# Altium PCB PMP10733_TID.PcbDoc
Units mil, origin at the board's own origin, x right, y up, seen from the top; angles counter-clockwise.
Board outline 1500 x 1500 mil, 2 copper layers (Top Layer, Bottom Layer), stack 62 mil thick; 37 components, 13 nets, 72 pads, 37 vias.
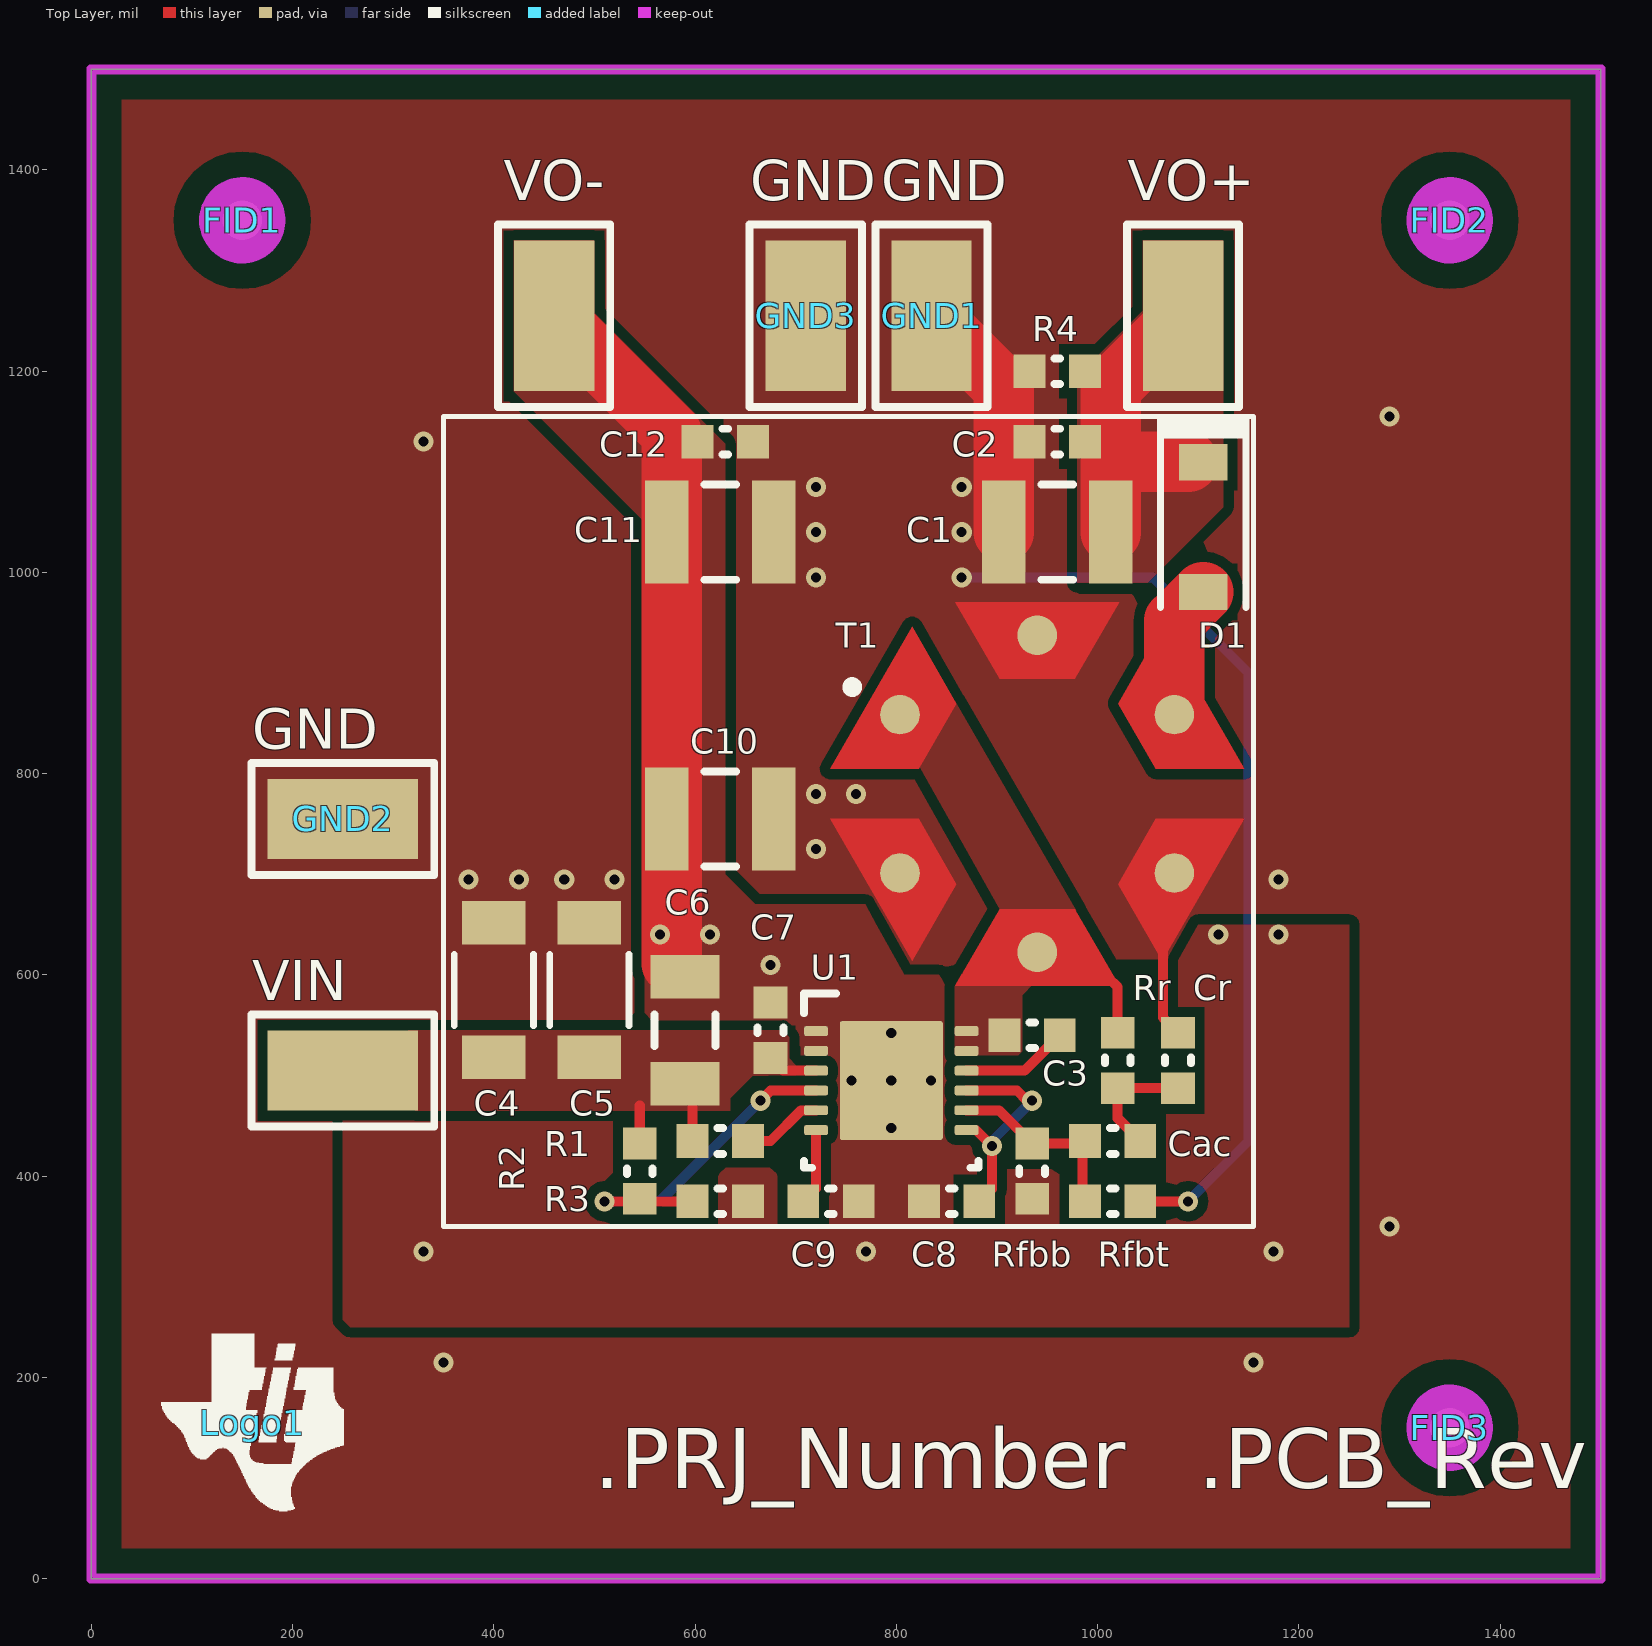
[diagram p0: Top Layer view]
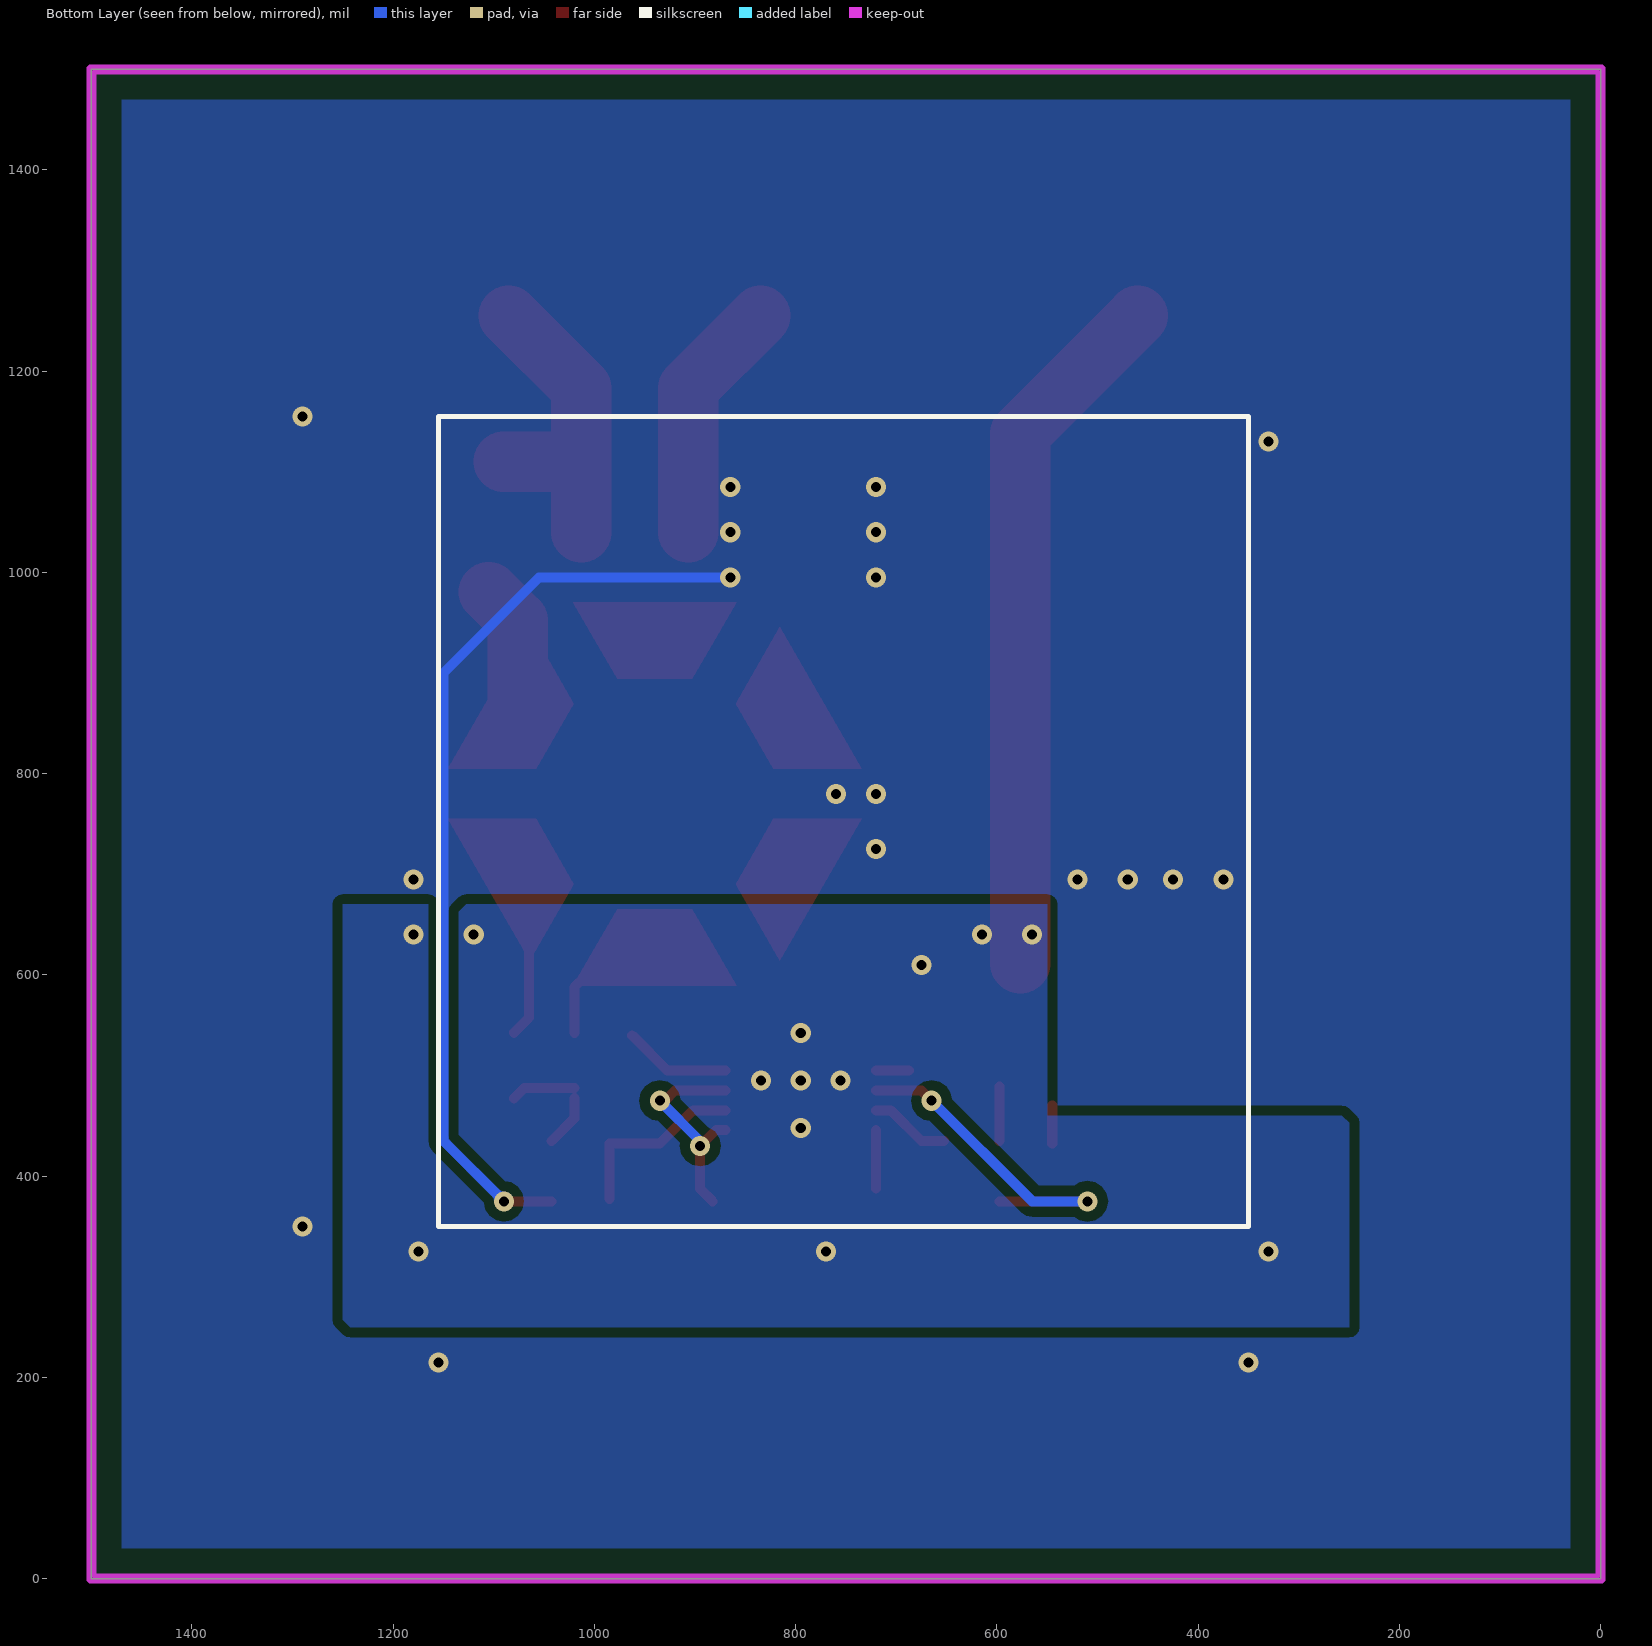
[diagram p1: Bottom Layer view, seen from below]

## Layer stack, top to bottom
Top Solder: solder mask 0.4, Solder Resist, Dk 3.5
Top Layer: signal copper 1.4
Dielectric1: core 59.2, FR-4, Dk 4.8
Bottom Layer: signal copper 1.4
Bottom Solder: solder mask 0.4, Solder Resist, Dk 3.5

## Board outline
0,0 1500,0 1500,1500 0,1500

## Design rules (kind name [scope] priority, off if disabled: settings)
AcuteAngle [All] p1: minimum=4.50000000000000E+0001 checktracksonly=FALSE
AssemblyTestPointUsage [All] p1: valid=2
Clearance Clearance_Keepouts [((IsTrack Or IsArc) And Not InPoly) And IsFree and IsKeepOut vs ((IsTrack Or IsArc) And Not InPoly) And IsFree and IsKeepOut] p1: gap=0
Clearance Clearance_BoardEdge_MountingHoles [OnCopper and InComponentClass('Mounting Holes') vs IsKeepOut] p2: gap=40
Clearance Clearance_BoardEdge_Poly [OnCopper and InPoly vs IsKeepOut] p3: gap=25
Clearance Clearance_BoardEdge [OnCopper and Not InComponentClass('Logo') and not InComponentClass('FiducialMark') and not InRegion(1000,500,4000,800) and Not IsKeepout vs IsKeepOut] p4: gap=75
Clearance Clearance_Poly [InPolygon] p5: gap=10
Clearance [All] p6: gap=7.87
ComponentClearance ComponentClearance_MountingHoles_FiducialMarks [InComponentClass('Mounting Holes') vs InComponentClass('FiducialMark')] p1: gap=50 collisioncheckmode=3 verticalgap=10 showdistances=FALSE
ComponentClearance ComponentClearance_Shunt [InComponentClass('Header') vs InComponentClass('Shunt')] p2: gap=0 collisioncheckmode=3 verticalgap=0 showdistances=FALSE
ComponentClearance ComponentClearance_Logo [InComponentClass('Logo')] p3: gap=50 collisioncheckmode=3 verticalgap=10 showdistances=FALSE
ComponentClearance ComponentClearance_ScrewToNut [(HasFootprint('NY PMS 440 0025 PH')) vs (HasFootprint('Keystone_1902C'))] p4: gap=5 collisioncheckmode=3 verticalgap=10 showdistances=FALSE
ComponentClearance ComponentClearance_MountingHoles [InComponentClass('Mounting Holes')] p5: gap=250 collisioncheckmode=3 verticalgap=100000 showdistances=FALSE
ComponentClearance ComponentClearance_SmallPassives [HasFootprint('0201*') or HasFootprint('0402*') or HasFootprint('0508') or HasFootprint('0603*') or HasFootprint('0612') or HasFootprint('0805*') or HasFootprint('0815*') or HasFootprint('0830*') or HasFootprint('1206*') or HasFootprint('1210*') or HasFootprint('1808*') or HasFootprint('1812*') or HasFootprint('1825*') or HasFootprint('2010*') or HasFootprint('2220*') or HasFootprint('2225*') or HasFootprint('2512*') or HasFootprint('2728*') or HasFootprint('3518*') vs HasFootprint('0201*') or HasFootprint('0402*') or HasFootprint('0508') or HasFootprint('0603*') or HasFootprint('0612') or HasFootprint('0805*') or HasFootprint('0815*') or HasFootprint('0830*') or HasFootprint('1206*') or HasFootprint('1210*') or HasFootprint('1808*') or HasFootprint('1812*') or HasFootprint('1825*') or HasFootprint('2010*') or HasFootprint('2220*') or HasFootprint('2225*') or HasFootprint('2512*') or HasFootprint('2728*') or HasFootprint('3518*')] p6: gap=15 collisioncheckmode=3 verticalgap=10 showdistances=FALSE
ComponentClearance ComponentClearance_THtoSMT [IsThruComponent vs IsSMTComponent] p7: gap=100 collisioncheckmode=3 verticalgap=30 showdistances=FALSE
ComponentClearance ComponentClearance_THtoTH [IsThruComponent vs IsThruComponent] p8: gap=118.11 collisioncheckmode=3 verticalgap=30 showdistances=FALSE
ComponentClearance [All] p9: gap=15 collisioncheckmode=3 verticalgap=10 showdistances=FALSE
DiffPairsRouting [All] p1: maxlimit=100 minlimit=10 mostfreqgap=10 toplayer_minwidth=15 toplayer_maxwidth=15 toplayer_prefwidth=15 bottomlayer_minwidth=15 bottomlayer_maxwidth=15 bottomlayer_prefwidth=15 maxuncoupledlength=1000
FabricationTestPointUsage TestPointUsage [All] p1: valid=2 allowmultiple=FALSE
FabricationTestpoint Testpoint [All] p1: side=3 testpointundercomponent=TRUE minsize=40 maxsize=100 preferedsize=60 minholesize=0 maxholesize=40 preferedholesize=32 testpointgrid=1 allowsidetop=TRUE allowsidebottom=TRUE usegrid=TRUE gridtolerance=0.01
FanoutControl Fanout_LCC [IsLCC] p1: bgadir=Out bgaviamode=Centered fanoutstyle=Auto fanoutdirection=Alternating viagrid=1 // Fanout_LCC (Default Rule)
FanoutControl Fanout_BGA [IsBGA] p2: bgadir=Out bgaviamode=Centered fanoutstyle=Auto fanoutdirection=Alternating viagrid=1 // Fanout_BGA (Default Rule)
FanoutControl Fanout_Default [All] p4: bgadir=Out bgaviamode=Centered fanoutstyle=Auto fanoutdirection=Alternating viagrid=1 // Fanout_Default (Default Rule)
FanoutControl Fanout_Small [(CompPinCount < 5)] p5: bgadir=Out bgaviamode=Centered fanoutstyle=Auto fanoutdirection=OutThenIn viagrid=1 // Fanout_Small (Default Rule)
HoleSize [All] p1: absolutevalues=TRUE maxlimit=251 minlimit=8 maxpercent=80.000 minpercent=20.000
MinimumAnnularRing MinimumAnnularRing_ThermalPadVias [IsVia and InAnyComponent] p1: minimumring=5
MinimumAnnularRing [All] p2: minimumring=5
MinimumSolderMaskSliver MinimumSolderMaskSliver_Logo [InComponentClass('Logo') vs InComponentClass('Logo')] p1: minsoldermaskwidth=0.7
MinimumSolderMaskSliver [All] p2: minsoldermaskwidth=3.94
PlaneConnect [All] p1: planeconnectstyle=Direct reliefexpansion=10 reliefentries=4 reliefconductorwidth=10 reliefairgap=10
PolygonConnect [All] p1: connectstyle=Direct reliefconductorwidth=10 reliefentries=4 polygonreliefangle="90 Angle" airgapwidth=10
RoutingVias ThermalPadVias [IsVia and InAnyComponent] p1: holewidth=7.87 width=19.68 viastyle="Through Hole" minholewidth=7.87 minwidth=19.68 maxholewidth=12.99 maxwidth=23.62
RoutingVias [All] p2: holewidth=16 width=34 viastyle="Through Hole" minholewidth=7.87 minwidth=20 maxholewidth=40 maxwidth=65
SilkToBoardRegionClearance [Not ((IsComment or IsDesignator) And (Hide <> 'False')) and not InRegion(1000,500,4000,800)] p1:
SilkToSilkClearance SilkToSilkClearance_Pb-FreeLogo [(HasFootprint('Pb-Free_Overlay_Medium') OR HasFootprint('Pb-Free_Overlay_Small')) vs (HasFootprint('Pb-Free_Overlay_Medium') OR HasFootprint('Pb-Free_Overlay_Small'))] p1: silktosilkclearance=0
SilkToSilkClearance [All] p2: silktosilkclearance=4
SilkToSolderMaskClearance "Silk to Solder Mask Opening" [All] p1: minsilkscreentomaskgap=3 clearancetoexposedcopper=FALSE
SolderMaskExpansion [All] p1: expansion=1.97
UnpouredPolygon [All] p1: allowunpoured=FALSE
Width [All] p1: maxlimit=100 minlimit=6 preferedwidth=10 checkconnectedcopper=TRUE
14 further rules are at their usual default settings.

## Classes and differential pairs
component class PMP10733_TID_Schematic: C1 C2 C3 C4 C5 C6 C7 C8 C9 C10 C11 C12 Cac Cr D1 GND1 GND2 GND3 R1 R2 R3 R4 Rfbb Rfbt Rr T1 U1 Vin VO+ VO-
component class Logo: Logo1
component class PMP10733_TID_Hardware: FID1 FID2 FID3 Logo1 ZZ2 ZZ3 ZZ4
component class FiducialMark: FID1 FID2 FID3
component class AssemblyNote: ZZ2 ZZ3 ZZ4

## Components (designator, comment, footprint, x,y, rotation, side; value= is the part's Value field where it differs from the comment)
C1 "GRM32ER71E226KE15L" 1210L 960,1040 r180 top
C2 "C1608X7R1H104K" 0603L 960,1130 r180 top
C3 "C1608X7R1H103K" 0603L 935,540 r180 top
C4 "C3216X7R1E106M160AE" 1206_190 400,585 r90 top
C5 "C3216X7R1E106M160AE" 1206_190 495,585 r90 top
C6 "GRM31CR71H475KA12L" 1206L 590,545 r90 top
C7 "C1608X7R1H104K" 0603L 675,545 r90 top
C8 "C1608X7R1E105K080AB" 0603L 855,375 r0 top
C9 "C1608X7R1H103K" 0603L 735,375 r0 top
C10 "GRM32ER71E226KE15L" 1210L 625,755 r180 top
C11 "" 1210L 625,1040 r180 top
C12 "C1608X7R1H104K" 0603L 630,1130 r180 top
Cac "C1608X7R1H102K" 0603L 1015,435 r180 top
Cr "GRM188R71H103KA01D" 0603L 1080,515 r270 top
D1 "RB160M-60TR" SOD-123 1105,1045 r270 top
FID1 "Fiducial" Fiducial10-20 150,1350 r0 top
FID2 "Fiducial" Fiducial10-20 1350,1350 r0 top
FID3 "Fiducial" Fiducial10-20 1350,150 r0 top
GND1 "GND" Keystone_5019 835,1255 r90 top
GND2 "GND" Keystone_5019 250,755 r0 top
GND3 "GND" Keystone_5019 710,1255 r90 top
Logo1 "Texas Instruments" TI_Symbol_Overlay_Small 160,155 r0 top
R1 "CRCW0603768KFKEA" 0603L 625,435 r0 top
R2 "CRCW060349K9FKEA" 0603L 545,405 r90 top
R3 "CRCW060322K6FKEA" 0603L 625,375 r180 top
R4 "CRCW06033K01FKEA" 0603L 960,1200 r0 top
Rfbb "CRCW060320K0FKEA" 0603L 935,405 r90 top
Rfbt "CRCW0603133KFKEA" 0603L 1015,375 r0 top
Rr "CRCW060320K0FKEA" 0603L 1020,515 r270 top
T1 "TA7848-AE" LPH8045-223 940,780 r60 top
U1 "LM5160DNTR" DNT0012B 795,495 r0 top
VIN "TESTPOINT" Keystone_5019 250,505 r0 top (schematic designator Vin)
VO+ "TESTPOINT" Keystone_5019 1085,1255 r90 top
VO- "TESTPOINT" Keystone_5019 460,1255 r90 top
ZZ2 "These assemblies are ESD sensitive, ESD precautions shall be observed." AssemblyNote 90,1994.11 r0 top
ZZ3 "These assemblies must be clean and free from flux and all contaminants. Use of no clean flux is not acceptable." AssemblyNote 90,1905.56 r0 top
ZZ4 "These assemblies must comply with workmanship standards IPC-A-610 Class 2, unless otherwise specified." AssemblyNote 90,1817 r0 top

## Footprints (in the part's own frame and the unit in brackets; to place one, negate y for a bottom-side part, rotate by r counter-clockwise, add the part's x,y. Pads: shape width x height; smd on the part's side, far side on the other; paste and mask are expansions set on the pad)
0603L [mm] "0603 from SM-752 data"
  rect 0.8x0.85 smd: 1(-0.7,0) 2(0.7,0)
  silkscreen extent -0.07,-0.33 0.07,0.33, body extent -0.87,-0.47 0.87,0.47, height 1
1206_190 [mm] "1206_190"
  rect 1.1x1.6 smd: 1(-1.7,0) 2(1.7,0)
  silkscreen extent -0.9,-1 0.9,1, body extent -1.75,-0.95 1.75,0.95, height 1.9
1206L [mm] "1206 from SM-752 data"
  rect 1.1x1.75 smd: 1(-1.35,0) 2(1.35,0)
  silkscreen extent -0.4,-0.77 0.4,0.77, body extent -1.7,-0.9 1.7,0.9, height 1.35
1210L [mm] "1210 from SM-752 data"
  rect 1.1x2.6 smd: 1(-1.35,0) 2(1.35,0)
  silkscreen extent -0.4,-1.2 0.4,1.2, body extent -1.7,-1.35 1.7,1.35, height 1.35
AssemblyNote [mil] "Assembly Note"
DNT0012B [mm] "SON, 12-Leads, Body 4x4mm, Pitch 0.5mm"
  rrect40% 0.6x0.25 smd: 1(-1.9,1.25) 2(-1.9,0.75) 3(-1.9,0.25) 4(-1.9,-0.25) 5(-1.9,-0.75) 6(-1.9,-1.25) 7(1.9,-1.25) 8(1.9,-0.75) 9(1.9,-0.25) 10(1.9,0.25) 11(1.9,0.75) 12(1.9,1.25)
  rrect4% 2.6x3 smd paste-1.3: 13(0,0)
  silkscreen extent -2.2,-2.2 2.2,2.2, body extent -2.05,-2.05 2.05,2.05, height 0.81
Fiducial10-20 [mm]
  round 1 smd mask+0.5: 1(0,0)
  Top Layer keep-out circle w1.178: c0,0 r0.5
Keystone_5019 [mm] "Test Point, Miniature, SMT"
  rect 3.8x2.03 smd: 1(0,0)
  silkscreen extent -2.31,-1.42 2.31,1.42, body extent -1.9,-1.02 1.9,1.02, height 2.29
LPH8045-223 [mm] "SMD, 6-Leads, Body 8.76x8.05mm"
  round 1 smd: 1(0,4) 2(-3.464,2) 3(-3.464,-2) 4(0,-4) 5(3.464,-2) 6(3.464,2)
  Top Layer region: -0.95,2.91 -2.07,4.84 2.07,4.84 0.95,2.91
  Top Layer region: -2.995,0.632 -5.227,0.627 -3.157,4.213 -2.045,2.278
  Top Layer region: -2.045,-2.278 -3.157,-4.213 -5.227,-0.627 -2.995,-0.632
  Top Layer region: 0.95,-2.91 2.07,-4.84 -2.07,-4.84 -0.95,-2.91
  Top Layer region: 2.995,-0.632 5.227,-0.627 3.157,-4.213 2.045,-2.278
  Top Layer region: 2.045,2.278 3.157,4.213 5.227,0.627 2.995,0.632
  silkscreen extent -0.12,5.27 0.12,5.51, body extent -4.03,-4.38 4.03,4.38, height 4.71
SOD-123 [mm] "On Semi recommended land pattern"
  rect 0.915x1.22 smd: 1(-1.637,0) 2(1.637,0)
  silkscreen extent -2.74,-1.17 2.03,1.17, body extent -1.93,-0.9 1.93,0.9, height 1.35
TI_Symbol_Overlay_Small [mil]
  silkscreen extent -90,-88 91,88

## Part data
C1 C10: "CAP, CERM, 22uF, 25V, +/-10%, X7R, 1210"
C2 C7 C12: "CAP, CERM, 0.1uF, 50V, +/-10%, X7R, 0603"
C3 C9 Cr: "CAP, CERM, 0.01uF, 50V, +/-10%, X7R, 0603"
C4 C5: "CAP, CERM, 10 µF, 25 V, +/- 20%, X7R, 1206_190"
C6: "CAP, CERM, 4.7 µF, 50 V, +/- 10%, X7R, 1206"
C8: "CAP, CERM, 1uF, 25V, +/-10%, X7R, 0603"
C11: library part GRM32ER71E226KE15L, "CAP, CERM, 22uF, 25V, +/-10%, X7R, 1210"
Cac: "CAP, CERM, 1000pF, 50V, +/-10%, X7R, 0603"
D1: "Diode, Schottky, 60 V, 1 A, SOD-123"
FID1 FID2 FID3: "Fiducial mark.  There is nothing to buy or mount."
GND1 GND2 GND3 VIN VO+ VO-: library part 5019, "Test Point, Miniature, SMT"
Logo1: library part TI_Logo, "Texas Instrument Corporate Signature"
R1: "RES, 768 k, 1%, 0.1 W, 0603"
R2: "RES, 49.9 k, 1%, 0.1 W, 0603"
R3: "RES, 22.6 k, 1%, 0.1 W, 0603"
R4: "RES, 3.01 k, 1%, 0.1 W, 0603"
Rfbb Rr: "RES, 20.0 k, 1%, 0.1 W, 0603"
Rfbt: "RES, 133 k, 1%, 0.1 W, 0603"
T1: "Coupled Inductor, 22uH, 1.35A Irms, 2A Isat, 1:1.05 turns ratio, LPH8045 Hexagonal Package"
U1: "Wide Input 65V, 1.5A Synchronous Step-Down DC-DC Converter, DNT0012B"
ZZ2 ZZ3 ZZ4: library part AssemblyNote

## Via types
v1: diameter 20, hole 10, Top Layer to Bottom Layer, 26 vias
v2: diameter 20, hole 10, Top Layer to Bottom Layer, tented both sides, 11 vias

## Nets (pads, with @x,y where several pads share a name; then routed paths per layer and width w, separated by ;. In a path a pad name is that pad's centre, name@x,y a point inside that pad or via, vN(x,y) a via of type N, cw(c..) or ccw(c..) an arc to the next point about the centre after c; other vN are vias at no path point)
BST: C3.1 U1.10 | length 107.3
  Top Layer w10: U1.10 927.4,504.84 C3.1
FB: Cac.2 Rfbb.2 Rfbt.1 U1.8 | length 183.9
  Top Layer w10: U1.8 902.09,465.47 Rfbb.2 985,432.56 Rfbt.1@985,377.44
GND: C1.2 C2.2 C4.2 C5.2 C10.1 C11.1 C12.1 Cr.1 GND1.1 GND2.1 GND3.1 R4.1 Rfbt.2 T1.2 T1.4 T1.6 | length 1265.1
  Top Layer w10: Rfbt.2 v1(1090,375) ; 1065,635 1065,557.56 Cr.1
  Top Layer w60: GND1.1 906.85,1183.15 C1.2
  Bottom Layer w10: v1(865,995) 1055,995 1150,900 1150,435 v1(1090,375)
  other v1: 375,695 425,695 470,695 520,695 720,725 720,780 760,780 720,995 720,1040 865,1040 720,1085 865,1085
  other v2: 350,215 1155,215 1290,350 1180,695 330,1130 1290,1155
NetCac_1: Cac.1 Cr.2 Rr.2 | length 115.9
  Top Layer w10: Rr.2@1020,477.44 1020,457.56 Cac.1 ; Rr.2 1070,487.44 Cr.2@1080,477.44
NetD1_2: D1.2 T1.5 | length 133.6
  Top Layer w60: T1.5 1076.38,951.91 D1.2
RON: R1.2 U1.5 | length 80.3
  Top Layer w10: R1.2 675,435 705.47,465.47 U1.5
SS: C9.1 U1.6 | length 58
  Top Layer w10: C9.1@720.2,387.76 U1.6
SW: C3.2 Rr.1 T1.1 T1.3 U1.11 U1.12 | length 59.6
  Top Layer w10: 1010,598 1020,588 Rr.1
UVLO: R2.1 R3.2 U1.4 | length 343.3
  Top Layer w10: v1(510,375) R3.2 ; v1(665,475) 675.16,485.16 U1.4
  Bottom Layer w10: v1(510,375) 565,375 v1(665,475)
VCC: C8.2 U1.7 U1.9 | length 222.9
  Top Layer w10: U1.7 879.21,445.79 v1(895,430) 895,387.44 C8.2 ; U1.9 919.84,485.16 930,475 v1(935,475)
  Bottom Layer w10: v1(895,430) 895,435 v1(935,475)
VIN: C4.1 C5.1 C6.1 C7.1 R1.1 R2.2 U1.3 VIN.1 | length 124.3
  Top Layer w10: R2.2 545,470 ; R1.1 C6.1@597.44,489.29 ; C7.1@687.6,504.84 U1.3
VO+: C1.1 C2.1 D1.1 R4.2 VO+.1 | length 314.8
  Top Layer w60: C1.1 1013.15,1183.15 VO+.1 ; 1020,1110 D1.1@1090,1110
VO-: C6.2 C7.2 C8.1 C9.2 C10.2 C11.2 C12.2 R3.1 Rfbb.1 U1.1 U1.2 U1.13 VO-.1 | length 692.1
  Top Layer w60: VO-.1 576.85,1138.15 576.85,1040 576.85,755 C6.2@576.85,611.3
  other v1: 795,447.76 755.63,495 795,495 834.37,495 795,542.25 675,610 565,640 615,640
  other v2: 330,325 770,325 1175,325 1120,640 1180,640
pads on no net: FID1.1 FID2.1 FID3.1

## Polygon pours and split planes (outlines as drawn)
GND on Top Layer "Top Layer-GND" (solid, remove dead copper, pour order 17): 0,1500 0,0 1500,0 1500,1500
VO- on Top Layer "Top Layer-VO-" (solid, remove dead copper, pour order 16): 250,455 250,250 1250,250 1250,650 1100,650 1072.22,600 807.78,600 780,650 768.89,670 760,670 700,670 700,455
VO- on Top Layer "Top Layer-VO-" (solid, remove dead copper, pour order 14): 705,550 550,550 550,950 550,1050 420,1180 420,1330 500,1330 500,1258 630,1128 630,890 630,700 660,670 710,670 720,670 730,670 730,520 705,520
VO+ on Top Layer "Top Layer-VO+" (solid, remove dead copper, pour order 13): 980,990 980,1195 1045,1260 1045,1330 1125,1330 1125,1080 1125,1065 1050,990
SW on Top Layer "Top Layer-SW" (solid, remove dead copper, pour order 12): 858,588.94 858,518 925,518 925,580 946,601 865,601
VIN on Top Layer "Top Layer-VIN" (solid, remove dead copper, pour order 11): 315,545 693.71,545 693.68,516.95 700.63,510 705,510 710,510 710,500 657.36,500 635.43,478.07 635,477.64 635,465 315,465
SW on Top Layer "Top Layer-SW" (solid, remove dead copper, pour order 10): 816.85,818.56 908.69,655 983.83,655 853.03,881.24
GND on Bottom Layer "Bottom Layer-GND" (solid, remove dead copper, pour order 18): 0,0 0,1500 1500,1500 1500,0
VO- on Bottom Layer "Top Layer-VO-" (solid, remove dead copper, pour order 15): 250,460 250,250 1250,250 1250,670 550,670 550,460

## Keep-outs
Keep-Out Layer:
  lines w5: -2.5,0 ccw(c0,0) 0,-2.5 ; -2.5,0 ccw(c0,0) 0,-2.5 ; -2.5,0 -2.5,1500 ; -2.5,1500 cw(c0,1500) 0,1502.5 ; -2.5,1500 cw(c0,1500) 0,1502.5 ; 0,-2.5 1500,-2.5 ; 0,1502.5 1500,1502.5 ; 1500,-2.5 ccw(c1500,0) 1502.5,0 ; 1500,-2.5 ccw(c1500,0) 1502.5,0 ; 1500,1502.5 cw(c1500,1500) 1502.5,1500 ; 1500,1502.5 cw(c1500,1500) 1502.5,1500 ; 1502.5,0 1502.5,1500 ; 2.5,2.5 1497.5,2.5 1497.5,1497.5 2.5,1497.5 2.5,2.5
  text ".Layer_Name" at 577,-858.49 h60

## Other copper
Top Layer:
  pour cut-out: 1015,403.46 1068.19,403.46 1068.19,350 1015,350
  pour cut-out: 1015,615 1080,615 1080,565 1015,565
  text ".Layer_Name" at 577,-858.49 h60
Bottom Layer:
  text ".Layer_Name" at 577,-858.49 h60

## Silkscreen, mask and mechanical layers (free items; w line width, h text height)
Top Overlay:
  lines w5: 350,350 1155,350 1155,1155 350,1155 350,350
  text ".PRJ_Number" at 500,90 h60
  text ".PCB_Rev" at 1100,90 h60
  text ".Layer_Name" at 577,-858.49 h60
Bottom Overlay:
  lines w5: 350,350 350,1155 1155,1155 1155,350 350,350
  text ".Layer_Name" at 577,-858.49 h60
Top Paste:
  text ".Layer_Name" at 577,-858.49 h60
Bottom Paste:
  text ".Layer_Name" at 577,-858.49 h60
Top Solder:
  text ".Layer_Name" at 577,-858.49 h60
  text ".Layer_Name" at 577,-858.49 h60
Bottom Solder:
  text ".Layer_Name" at 577,-858.49 h60
Drill Guide:
  text ".Layer_Name" at 577,-858.49 h60
M1 Board Outline:
  the board outline again, w10
  text ".Layer_Name" at 577,-858.49 h60
M2 Board Dimensions:
  rectangle: 0,-275 125,-150
  rectangle: 125,-400 500,-275
  lines w7: 0,-275 1000,-275 ; 125,-400 125,-150 ; 250,-400 250,-150 ; 500,-400 500,-150 ; 750,-400 750,-150 ; 0,-400 1000,-400 1000,-150 0,-150 0,-400
  text ".Layer_Name" at 577,-858.49 h60
M3 3D STEP Top:
  text ".Layer_Name" at 577,-858.49 h60
M4 3D STEP Bottom:
  text ".Layer_Name" at 577,-858.49 h60
M5 Assembly Top:
  lines w10: -292,-930.17 6308,-930.17 ; -292,-726.83 6310,-726.83 ; -292,-523.5 -292,-1133.5 3713,-1133.5 6310,-1133.5 6310,-523.5 -291.5,-523.5 -291.5,-1133.5 1284,-1133.5 ; 2173,-1133.5 2173,-523.5 ; 3440,-726.83 3440,-523.5 ; 4280,-726.83 4280,-523.5 ; 4902,-1140 4902,-937.17
  text "COMPONENTS MARKED 'DNP' SHOULD NOT BE POPULATED." at 1153.5,-318.5 h60
  text "ASSEMBLY VARIANT:" at 1153,-434 h60
  text ".VariantName" at 2189,-434 h60
  text "PCB VIEWED FROM TOP SIDE" at -228.5,-655.67 h60
  text "BOARD #:" at 2248,-655.67 h60
  text ".PRJ_Number" at 2793.5,-655.67 h60
  text "REV:" at 3638,-655.67 h60
  text ".PCB_Rev" at 3929.5,-655.67 h60
  text "SVN REV:" at 4476,-655.67 h60
  text ".VersionControl_RevNumber" at 4982,-655.67 h60
  text "TID #:" at 2248,-859 h60
  text ".TID" at 2793.5,-859 h60
  text "PLOT NAME =" at -228.5,-1064.34 h60
  text ".plot_File_Name" at 577,-1064.34 h60
  text "GENERATED    :" at 2250,-1064.34 h60
  text ".Print_Date" at 3119.5,-1064.34 h60
  text ".Print_Time" at 3848.5,-1064.34 h60
  text "TEXAS INSTRUMENTS" at 5113,-1064.34 h60
M6 Assembly Bottom:
  lines w10: -292.5,-727.33 6309.5,-727.33 ; -290.5,-930.67 6309.5,-930.67 ; 1115.5,-1140.5 1115.5,-937.67 ; 1737.5,-727.33 1737.5,-524 ; 2577.5,-727.33 2577.5,-524 ; 3844.5,-1134 3844.5,-524 ; 4733.5,-1134 6309,-1134 6309,-524 -292.5,-524 -292.5,-1134 2304.5,-1134 6309.5,-1134 6309.5,-524
  text "COMPONENTS MARKED 'DNP' SHOULD NOT BE POPULATED." at 6102,-318 h60
  text ".VariantName" at 5058,-434 h60
  text "ASSEMBLY VARIANT:" at 6097,-434 h60
  text ".VersionControl_RevNumber" at 1035.5,-656.17 h60
  text "SVN REV:" at 1541.5,-656.17 h60
  text ".PCB_Rev" at 2088,-656.17 h60
  text "REV:" at 2379.5,-656.17 h60
  text ".PRJ_Number" at 3224,-656.17 h60
  text "BOARD #:" at 3769.5,-656.17 h60
  text "PCB VIEWED FROM BOTTOM SIDE" at 6246,-656.17 h60
  text ".TID" at 3224,-859.5 h60
  text "TID #:" at 3769.5,-859.5 h60
  text "TEXAS INSTRUMENTS" at 904.5,-1064.84 h60
  text ".Print_Time" at 2169,-1064.84 h60
  text ".Print_Date" at 2898,-1064.84 h60
  text "GENERATED    :" at 3767.5,-1064.84 h60
  text ".plot_File_Name" at 5440.5,-1064.84 h60
  text "PLOT NAME =" at 6246,-1064.84 h60
M9 Title Sheet:
  drawing of 57 lines, arcs and shapes, not listed
  text "1" at 739.84,8036.5 h70
  text "2" at 3235.5,8036.5 h70
  text "3" at 5724.84,8036.5 h70
  text "4" at 8231.51,8036.5 h70
  text "5" at 10730.5,8036.5 h70
  text "6" at 13235.5,8036.5 h70
  text "A" at -416.5,6893.5 h70
  text "A" at 14383.5,6893.5 h70
  text "B" at -416.5,4513.5 h70
  text "B" at 14383.5,4513.5 h70
  text "C" at -416.5,2138.5 h70
  text "C" at 14383.5,2138.5 h70
  text "PROJECT TITLE:" at 11343.5,277.5 h45
  text ".PRJ_Title" at 11393.5,144.17 h70
  text "DESIGNED FOR:" at 11343.5,-23.5 h45
  text ".PRJ_Customer" at 11393.5,-163.5 h70
  text "D" at -416.5,-231.5 h70
  text "D" at 14383.5,-231.5 h70
  text "FILE NAME:" at 11343.5,-323.5 h45
  text ".PCB_File_Name_No_Path" at 11393.5,-443.5 h70
  text "Texas Instruments (TI) and/or its licensors do not warrant the accuracy or completeness of this specification" at 6374,-605.34 h45
  text "ENGINEER:" at 11343.5,-613.5 h45
  text "LAYOUT BY:" at 12848.5,-613.5 h45
  text "or any information contained therein. TI and/or its licensors do not warrant that this design will meet" at 6329.01,-718 h45
  text ".PRJ_Engineer" at 11393.5,-768.49 h70
  text ".PCB_Layout" at 12899,-768.49 h70
  text "the specifications, will be suitable for your application or fit for any particular purpose, or will operate in" at 6329.01,-830.67 h45
  text ".Layer_Name" at 577,-858.49 h60
  text "ALTIUM DESIGNER VERSION:" at 12848.5,-923.5 h45
  text "an implementation. TI and/or its licensors do not warrant that the design is production worthy. You should" at 6329.01,-943.33 h45
  text "completely validate and test your design implementation to confirm the system functionality for your application." at 6374,-1056 h45
  text ".print_Scale" at 11393.5,-1056.83 h70
  text ".Application_BuildNumber" at 12899,-1056.83 h70
  text "1" at 739.84,-1263.5 h70
  text "2" at 3235.5,-1263.5 h70
  text "3" at 5724.84,-1263.5 h70
  text "4" at 8231.51,-1263.5 h70
  text "5" at 10730.5,-1263.5 h70
  text "6" at 13235.5,-1263.5 h70
M10 Fab Notes:
  drawing of 185 lines, arcs and shapes, not listed
  text "DESIGN INFORMATION" at 12381.02,5910 h60
  text "MIN. TRACK WIDTH:" at 11736.46,5730 h60
  text "10" at 12832.7,5730 h60
  text "MIL" at 12987.46,5730 h60
  text "MIN. CLEARANCE:" at 11736.46,5598 h60
  text "0.2" at 12772.7,5598 h60
  text "mm" at 12987.46,5598 h60
  text "MIN. VIA PAD SIZE:" at 11736.46,5466 h60
  text "20" at 12802.71,5466 h60
  text "MIL" at 12987.46,5466 h60
  text "0.13mm (5MIL)" at 12431.46,5324.29 h60
  text "MINIMUM ANNULAR RING" at 11407.23,5320 h60
  text "EXTERNAL" at 13139.46,5320 h60
  text "PER" at 11607.23,5202 h60
  text "IPC-D-275 CLASS 2 LEVEL C" at 11827.23,5202 h60
  text "MIL, HOLES" at 13315.46,5089.71 h60
  text "+/-" at 12923,5089 h60
  text "+/-" at 13777,5089 h60
  text "REGISTRATION TOLERANCES:" at 11407.23,5084 h60
  text "METAL" at 12607,5084 h60
  text "5" at 13183.2,5084 h60
  text "3" at 14016.2,5084 h60
  text "MIL" at 14132.46,5084 h60
  text "MATERIAL:" at 11332.46,4874.54 h60
  text "FR-4 High Tg" at 12318.9,4734.21 h60
  text "FR-4" at 13583.9,4729.21 h60
  text "FR-408" at 11753.46,4725.64 h60
  text "OTHER" at 13241.46,4725.64 h60
  text "X" at 13055,4725 h60
  text "62 MIL (1.6mm) +/-10%" at 12073.56,4562.92 h60
  text "THICKNESS:" at 11407.23,4558.64 h60
  text "X" at 11945.4,4558.64 h60
  text "OTHER" at 13358.46,4558.64 h60
  text "TOLERANCE:" at 11407.23,4400.64 h60
  text "X" at 12246.53,4400.64 h60
  text "ANSI IPC-6012 TYPE 3 CLASS 2" at 12433.48,4400.64 h60
  text "OTHER +/-" at 12433.46,4244.64 h60
  text "BOW & TWIST:" at 11407.23,4087.64 h60
  text "X" at 12246.53,4087.64 h60
  text "ANSI IPC-6012 TYPE 3 CLASS 2" at 12433.48,4087.64 h60
  text "OTHER +/-" at 12433.46,3929.13 h60
  text "DRILLING:" at 11332.46,3790.64 h60
  text "REFERENCE:" at 11407.23,3673.64 h60
  text "X" at 12055.46,3673.64 h60
  text "AS SHOWN" at 12242.46,3673.64 h60
  text "X" at 12956.46,3673.64 h60
  text "NC_DRILL FILES" at 13093.46,3673.64 h60
  text "PTH MIN COPPER THICKNESS:" at 11407.23,3515.64 h60
  text "X" at 12757.46,3515.64 h60
  text "1MIL" at 12894.46,3515.64 h60
  text "OTHER" at 13391.46,3515.64 h60
  text "BOARD FINISH:" at 11332.46,3356.64 h60
  text "SILKSCREEN:" at 11487.68,3238.64 h60
  text "X" at 12436.46,3238.64 h60
  text "TOP" at 12562.46,3238.64 h60
  text "X" at 12946.46,3238.64 h60
  text "BOTTOM" at 13073.46,3238.64 h60
  text "SILKSCREEN COLOR:" at 11487.68,3071.64 h60
  text "X" at 12435.42,3071.64 h60
  text "WHITE" at 12562.46,3071.64 h60
  text "OTHER" at 13073.46,3071.64 h60
  text "SOLDER RESIST COLOR:" at 11487.68,2901.64 h60
  text "X" at 12055.42,2742.44 h60
  text "GREEN" at 12182.46,2742.44 h60
  text "BLUE" at 12773.46,2742.44 h60
  text "OTHER" at 13311.46,2742.44 h60
  text "IMMERSION GOLD (ENIG)" at 12393.46,2553.92 h60
  text "ENEPIG" at 13731,2550.64 h60
  text "SURFACE FINISH:" at 11332.46,2549.64 h60
  text "X" at 12206.51,2549.64 h60
  text "IMM. TIN/SILVER OR EQUIV" at 11662,2392.64 h60
  text "OTHER" at 13093.46,2392.64 h60
  text "ARRAY/PANEL:" at 11332.46,2213.64 h60
  text "CUT AND TRIM PER MECH LAYER 1" at 12393.46,2209.35 h60
  text "N.C. ROUTE" at 12393.46,2057.64 h60
  text "X" at 13072.46,2057.64 h60
  text "V. SCORE" at 13259.46,2057.64 h60
  text "CERTIFICATION:" at 11332.46,1920.64 h60
  text "MATERIALS AND WORKMANSHIP FOR ALL PCBS" at 12057.46,1920.64 h60
  text "TO MEET OR EXCEED THE REQUIREMENTS OF:" at 12057.46,1822.64 h60
  text "X" at 11683.96,1686.13 h60
  text "ANSI IPC-A-600F CLASS ->" at 11822.96,1686.13 h60
  text "X" at 13462.02,1686.13 h60
  text "2" at 13580.96,1686.14 h60
  text "1" at 13265.96,1684.64 h60
  text "3" at 13934.96,1684.64 h60
  text "X" at 11686.02,1526.64 h60
  text "UL 94V-0" at 11822.96,1526.64 h60
  text "X" at 12498.02,1526.64 h60
  text "RoHS" at 12634.96,1526.64 h60
  text "OTHER" at 13279.36,1526.64 h60
  text "PER ORDER" at 13676.42,1526.64 h60
  text "ADDITIONAL REQUIREMENTS:" at 11332.46,1385.64 h60
  text "MICROSECTION:" at 11407.23,1270.64 h60
  text "YES" at 12312.96,1270.64 h60
  text "REQUIRED" at 13174.46,1114.49 h60
  text "BARE BOARD ELEC. TEST:" at 11407.23,1111.64 h60
  text "NONE" at 12712.96,1111.64 h60
  text "X" at 13047.46,1111.64 h60
  text "PER ORDER" at 13766.46,1111.64 h60
  text "MANUFACTURER'S UL:" at 11407.23,954.64 h60
  text "RAIL" at 12572.96,950.35 h60
  text "METAL" at 13064.77,950.35 h60
  text "X" at 13440,950 h60
  text "SILK" at 13576.46,950.35 h60
  text ".Layer_Name" at 577,-858.49 h60
M11 Gerber Information:
  lines w10: -292,-930.17 6308,-930.17 ; -292,-726.83 6310,-726.83 ; -292,-523.5 -292,-1133.5 3713,-1133.5 6310,-1133.5 6310,-523.5 -291.5,-523.5 -291.5,-1133.5 1284,-1133.5 ; 2173,-1133.5 2173,-523.5 ; 3440,-726.83 3440,-523.5 ; 4280,-726.83 4280,-523.5 ; 4902,-1140 4902,-937.17
  text "ALL ARTWORK VIEWED FROM TOP SIDE" at -228.5,-655.67 h60
  text "BOARD #:" at 2248,-655.67 h60
  text ".PRJ_Number" at 2793.5,-655.67 h60
  text "REV:" at 3638,-655.67 h60
  text ".PCB_Rev" at 3929.5,-655.67 h60
  text "SVN REV:" at 4476,-655.67 h60
  text ".VersionControl_RevNumber" at 4982,-655.67 h60
  text "LAYER NAME =" at -228.5,-858.49 h60
  text "TID #:" at 2248,-859 h60
  text ".TID" at 2793.5,-859 h60
  text "PLOT NAME =" at -228.5,-1064.34 h60
  text ".plot_File_Name" at 577,-1064.34 h60
  text "GENERATED    :" at 2250,-1064.34 h60
  text ".Print_Date" at 3119.5,-1064.34 h60
  text ".Print_Time" at 3848.5,-1064.34 h60
  text "TEXAS INSTRUMENTS" at 5113,-1064.34 h60
M12 Stackup:
  drawing of 191 lines, arcs and shapes, not listed
  text "Layer" at 9790.58,7830 h60
  text "Name" at 10200.49,7830 h60
  text "Material" at 11130.23,7830 h60
  text "Thickness" at 11990,7830 h60
  text "Constant" at 12639.84,7830 h60
  text "Board Layer Stack" at 13209.7,7830 h60
  text "1" at 9790.58,7710 h60
  text "Top Overlay" at 10200.49,7710 h60
  text "2" at 9790.58,7590 h60
  text "Top Solder" at 10200.49,7590 h60
  text "Solder Resist" at 11130.23,7590 h60
  text "0.40mil" at 11990,7590 h60
  text "3.5" at 12639.84,7590 h60
  text "3" at 9790.58,7470 h60
  text "Top Layer" at 10200.49,7470 h60
  text "Copper" at 11130.23,7470 h60
  text "1.40mil" at 11990,7470 h60
  text "4" at 9790.58,7350 h60
  text "Dielectric1" at 10200.49,7350 h60
  text "FR-4" at 11130.23,7350 h60
  text "59.20mil" at 11990,7350 h60
  text "4.8" at 12639.84,7350 h60
  text "5" at 9790.58,7230 h60
  text "Bottom Layer" at 10200.49,7230 h60
  text "Copper" at 11130.23,7230 h60
  text "1.40mil" at 11990,7230 h60
  text "6" at 9790.58,7110 h60
  text "Bottom Solder" at 10200.49,7110 h60
  text "Solder Resist" at 11130.23,7110 h60
  text "0.40mil" at 11990,7110 h60
  text "3.5" at 12639.84,7110 h60
  text "7" at 9790.58,6990 h60
  text "Bottom Overlay" at 10200.49,6990 h60
  text ".Layer_Name" at 577,-858.49 h60
M13 Component Bodies Top:
  text ".Layer_Name" at 577,-858.49 h60
M14 Component Bodies Bottom:
  text ".Layer_Name" at 577,-858.49 h60
M15 Courtyards Top:
  text ".Layer_Name" at 577,-858.49 h60
M16 Courtyards Bottom:
  text ".Layer_Name" at 577,-858.49 h60
Drill Drawing:
  lines w10: 1767.83,1246.16 1817.6,1246.16 1817.6,1295.93 1767.83,1295.93 1767.83,1246.16
  lines w12: 1700,1201.36 3818.02,1201.36 ; 1700,1350.68 3818.02,1350.68 ; 2070.36,1052.04 2070.36,1500 ; 2427.36,1052.04 2427.36,1500 ; 3088.93,1052.04 3088.93,1500 ; 3373.07,1052.04 3373.07,1500 ; 1700,1052.04 3818.02,1052.04 3818.02,1500 1700,1500 1700,1052.04
  text "Symbol" at 1789.59,1395.48 h72
  text "Quantity" at 2115.16,1395.48 h72
  text "Finished Hole Size" at 2472.16,1395.48 h72
  text "Plated" at 3133.72,1395.48 h72
  text "Hole Type" at 3417.86,1395.48 h72
  text "37" at 2115.16,1246.16 h60
  text "10.00mil (0.254mm)" at 2472.16,1246.16 h60
  text "PTH" at 3133.72,1246.16 h60
  text "Round" at 3417.86,1246.16 h60
  text "37 Total" at 2115.16,1096.84 h60
  text ".Layer_Name" at 577,-858.49 h60

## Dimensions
1155,350 to 1155,1155 on Top Overlay
350,350 to 1155,350 on Top Overlay
0,-400 to 1000,-400 on M2 Board Dimensions
0,0 to 0,1500 on M2 Board Dimensions
0,0 to 1500,0 on M2 Board Dimensions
